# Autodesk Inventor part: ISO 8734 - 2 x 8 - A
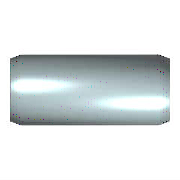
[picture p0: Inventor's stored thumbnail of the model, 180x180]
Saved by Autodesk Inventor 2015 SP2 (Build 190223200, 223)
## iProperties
IsCustomPart: 0
Created: 2012-02
Part Number: ISO 8734 - 2 x 8 - A
Material: Stahl
Description: Zylinderstift
Document SubType Name: Modeling
Standard: ISO 8734
Designer: rYan
Standards Organization: DIN
Language: de-DE
Size Designation: 2 x 8 - A
Categories: <MemberInstance><Categories><Category DisplayName="Verbindungselemente" InternalName="e4da775c-781d-43d5-af7c-5136215cf5a6" Mnemonic="FSTN"><Category DisplayNam
Density: 7.85 g/cm^3
Mass: 0.195724 g
Surface Area: 0.553671 cm^2
Volume: 0.024933 cm^3
Appearance: Platte
Author: rYan
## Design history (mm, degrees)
sketch "Skizze"
  geometry: C1 r 1 at (0, 0); 1 further point
  constraints: 1 centre point, 1 coincident
  dimensions: "d1" = 2 diameter of C1 (= NND)
extrude "Körper" new body sketch "Skizze" distance "d2" = 8 (= NLG); taper "d3" = 0 deg
body "Solid1"
chamfer "Fase1" distance "d4" = 0.35 (= PHH); stored, may be unused: angle "d5" = 15 deg (= FAWI), second distance "d11" = 0.35 (= PHH)
chamfer "Fase2" distance "d8" = 0.35 (= PHH); stored, may be unused: angle "d9" = 15 deg (= FAWI), second distance "d12" = 0.35 (= PHH)
other parameters: "NND" = 2 [user parameter; used in 1 equation term], "NLG" = 8 [user parameter; used in 1 equation term], "PHH" = 0.35 [user parameter; used in 5 equation terms], "FAWI" = 15 deg [user parameter; used in 2 equation terms], "d13" = 0, "d15" = 0, "d16" = 0, "PHH2" = 0.35 (= PHH) [user parameter], "FAWI2" = 15 deg [user parameter]
